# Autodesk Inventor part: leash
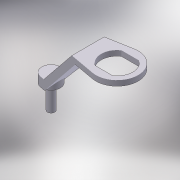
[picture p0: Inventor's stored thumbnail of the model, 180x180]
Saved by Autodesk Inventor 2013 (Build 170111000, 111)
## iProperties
Shininess: 50.0
Length Units: 11269
Angle Units: 11279
Time Units: 11290
Mass Units: 11283
Length Display Precision: 3
Angle Display Precision: 2
Created: 2002-03
Part Number: leash
Material: Aluminum-6061
Document SubType Name: Modeling
Designer: =<Author>
Density: 2.71 g/cm^3
Description: =<Part Number>
Density: 2.71
Volumn: 46.79128752129502
Area: 118.75369394846867
PropertySet Name: Model Information
Control State: 0
Master: False
Checked Out: True
Last Check In Date: 2008-10-15
Checked Out Date: 2008-10-15
Author: LAlexey
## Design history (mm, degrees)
sketch "Sketch1"
  geometry: L1 (3.605, 18.788)-(51.985, 27.641); L2 (51.985, -3.836)-(3.605, 5.017); L3 (48.232, 1.903)-(61.498, 1.903); L4 (48.232, 21.903)-(61.498, 21.903); A1 r 7 centre (4.865, 11.903) between (3.605, 18.788) and (3.605, 5.017); A2 r 16 centre (54.865, 11.903) between (51.985, -3.836) and (51.985, 27.641); A3 r 12 centre (54.865, 11.903) between (61.498, 1.903) and (61.498, 21.903); A4 r 12 centre (54.865, 11.903) between (48.232, 21.903) and (48.232, 1.903)
  constraints: 8 end point, 8 point on circle, 4 centre point, 4 tangent, 2 parallel, 1 coincident, 1 horizontal
  dimensions: "d0" = 16 radius of A2; "d1" = 7 radius of A1; "d2" = 0 vertical distance of A2.centre A1.centre; "d3" = 50 distance of A2.centre A1.centre; "d6" = 12 radius of A3; "d7" = 12 radius of A4; "d23" = 20 distance between parallel lines of L4 L3
extrude "Extrusion1" new body sketch "Sketch1" distance "d8" = 38; taper "d9" = 0 deg
workaxis "Work Axis1"
workaxis "Work Axis2"
workplane "Work Plane1"
sketch "Sketch2"
  geometry: L1 (1.26, 38)-(-47.12, 38) reference; L2 (-66, 38)-(-47.12, 38) reference; L3 (1.26, 38)-(7, 38) reference; L4 (-66, 38)-(-66, 34); L5 (-66, 34)-(-31.171, 34); L6 (-31.171, 34)-(-2.655, 0); L7 (-47.12, 0)-(1.26, 0) reference; L8 (7, 0)-(1.26, 0) reference; L9 (7, 0)-(7, 7); L10 (7, 7)-(-2, 7); L11 (-2, 7)-(-28, 38); L12 (-28, 38)-(-66, 38); L13 (-47.12, 0)-(-66, 0) reference; L14 (-2.655, 0)-(-66, 0); L15 (-66, 0)-(-66, 34); L16 (7, 7)-(7, 38); L17 (-66, 38)-(7, 38)
  constraints: 22 end point, 6 perpendicular, 3 parallel, 2 point on line, 1 collinear
  dimensions: "d10" = 38 distance from line of L4 L11.end; "d11" = 4 distance between parallel lines of L1 L5; "d12" = 7 distance between parallel lines of L7 L10; "d13" = 5 distance between parallel lines of L6 L11; "d14" = 9 distance from line of L10.end L9
extrude "Extrusion2" cut sketch "Sketch2" stored distance "d15" = 100; taper "d16" = 0 deg
sketch "Sketch3"
  geometry: C1 r 7 at (0, 0); A1 r 7 centre (0, 0) between (-1.26, 6.886) and (-1.26, -6.886) reference
  constraints: 1 centre point, 1 concentric
  dimensions: "d17" = 14 diameter of C1
extrude "Extrusion3" join sketch "Sketch3" distance "d18" = 7; taper "d19" = 0 deg
sketch "Sketch4"
  geometry: C1 r 2.75 at (-4.865, 11.903); A1 r 7 centre (-4.865, 11.903) between (-3.605, 5.017) and (-3.605, 18.788) reference
  constraints: 1 centre point, 1 coincident
  dimensions: "d20" = 5.5 diameter of C1
extrude "Extrusion4" join sketch "Sketch4" distance "d21" = 18; taper "d22" = 0 deg
body "Solid1"
other parameters: "d4" = 24
